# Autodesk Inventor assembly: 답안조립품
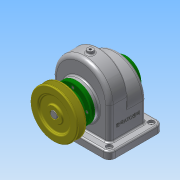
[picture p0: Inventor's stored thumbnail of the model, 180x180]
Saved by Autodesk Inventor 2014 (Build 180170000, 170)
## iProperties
Created: 2017-11
Part Number: 답안조립품
Document SubType Name: Assembly
Designer: sda
Author: sda
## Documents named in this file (14)
- C:\Users\sda\Desktop\471107V1028\답안조립품.iam
- C:\Users\sda\Desktop\471107V1028\본체.ipt
- C:\Users\sda\Desktop\471107V1028\스퍼기어.ipt
- C:\Users\sda\Desktop\471107V1028\축.ipt
- C:\Users\sda\Desktop\471107V1028\키 - 6 x 6 x 22.ipt
- C:\Users\sda\Desktop\471107V1028\베어링 6002.ipt
- C:\Users\sda\Desktop\471107V1028\V-벨트풀리.ipt
- C:\Users\sda\Desktop\471107V1028\멈춤나사 - M4 x 10.ipt
- 멈춤나사 - M4 x 10.ipt
- C:\Users\sda\Desktop\471107V1028\키 - 5 x 5 x 18.ipt
- C:\Users\sda\Desktop\471107V1028\뒤커버.ipt
- C:\Users\sda\Desktop\471107V1028\앞커버.ipt
- C:\Users\sda\Desktop\471107V1028\볼트 M3 x 8.ipt
- C:\Users\sda\Desktop\471107V1028\오일 실 15 30 7.ipt
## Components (1 placed, 1 different names)
1. V-벨트풀리:1 — 플러쉬:1
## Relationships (1: Flush 1)
- 플러쉬:1 [Flush]: V-벨트풀리:1
